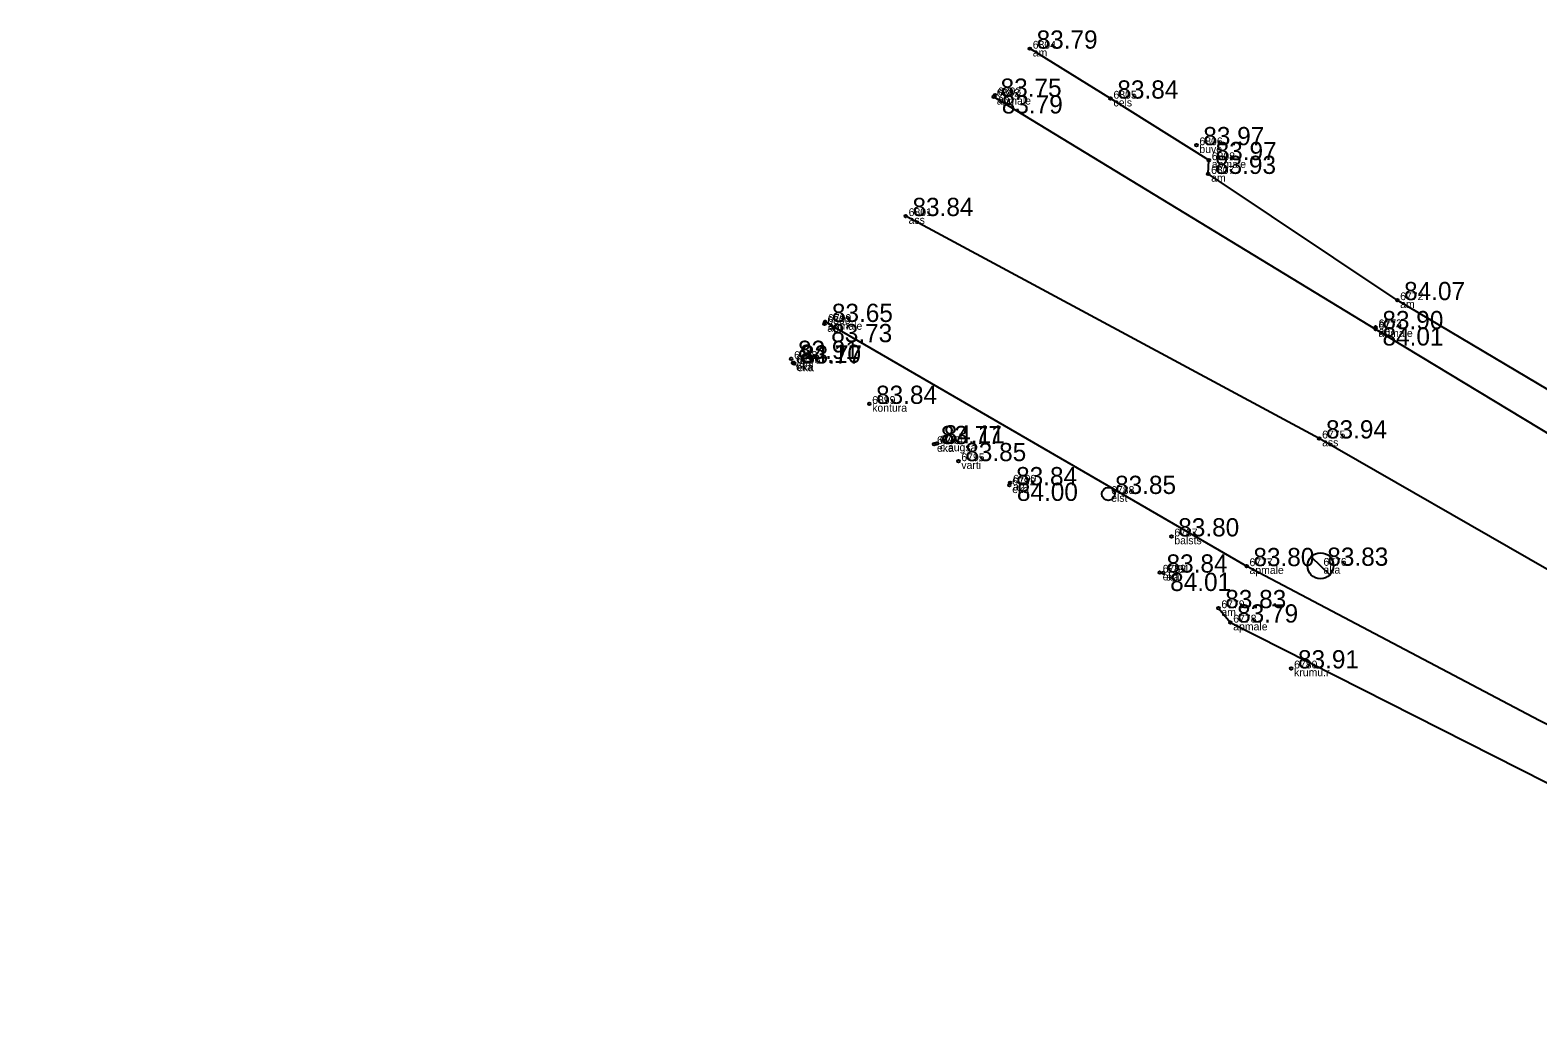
# Model space of a CAD drawing. Extents: x 614911 to 615803, y 262110 to 264311.
# Drawn here: x 615140.5 to 615198.4, y 262553.3 to 262591 of the extents above; entities that cross this region are included whole.
import ezdxf

# ---------------------------------------------------------------- set-up
doc = ezdxf.new("R2010")
doc.units = 0
for name, color, linetype in [('Level 12', 7, 'Continuous'), ('Level 18', 7, 'Continuous'), ('Level 37', 7, 'Continuous'), ('Level 53', 7, 'Continuous'), ('Level 54', 7, 'Continuous'), ('Level 57', 7, 'Continuous'), ('Level 58', 7, 'Continuous')]:
    doc.layers.add(name, color=color, linetype=linetype)

msp = doc.modelspace()

# ---------------------------------------------------------------- linework, layer by layer
at = {"layer": 'Level 12'}
for p, q in [((615189.679, 262570.789), (615190.397, 262570.093)), ((615190.038, 262570.441), (615190.037, 262570.44))]:
    msp.add_line(p, q, dxfattribs=at)
msp.add_circle((615190.038, 262570.441), 0.5, dxfattribs=at)
at = {"layer": 'Level 18'}
msp.add_circle((615181.889, 262573.199), 0.25, dxfattribs=at)
at = {"layer": 'Level 37'}
for p, q in [((615186.12, 262568.814), (615186.576, 262568.261)), ((615186.576, 262568.261), (615202.324, 262560.29))]:
    msp.add_line(p, q, dxfattribs=at)
for points in [[(615208.683, 262572.181), (615199.6, 262576.716), (615192.986, 262580.641), (615185.727, 262585.487), (615185.75, 262586.016), (615181.977, 262588.379), (615178.877, 262590.297)], [(615177.494, 262588.45), (615192.153, 262579.526), (615207.523, 262570.238), (615220.011, 262562.863), (615221.634, 262562.045), (615224.342, 262561.098), (615229.242, 262561.003), (615229.462, 262561.056)], [(615216.216, 262560.276), (615189.988, 262575.33), (615174.111, 262583.87)], [(615134.751, 262536.316), (615136.666, 262532.387), (615152.21, 262536.845), (615168.777, 262541.517), (615176.69, 262543.827), (615195.4, 262549.214), (615198.892, 262550.172), (615209.293, 262553.06), (615211.306, 262553.645), (615214.425, 262554.554), (615214.157, 262556.702), (615205.474, 262561.046), (615198.438, 262564.498), (615187.2, 262570.428), (615171.016, 262579.803)]]:
    msp.add_lwpolyline(points, dxfattribs=at)
at = {"layer": 'Level 57'}
for centre in [(615178.877, 262590.297), (615177.494, 262588.45), (615177.54, 262588.508), (615181.977, 262588.379), (615185.277, 262586.59), (615185.727, 262585.487), (615185.75, 262586.016), (615174.111, 262583.87), (615192.986, 262580.641), (615170.99, 262579.726), (615171.016, 262579.803), (615192.153, 262579.526), (615192.158, 262579.599), (615169.714, 262578.384), (615169.791, 262578.231), (615169.83, 262578.206), (615172.713, 262576.657), (615175.201, 262575.113), (615175.309, 262575.14), (615189.988, 262575.33), (615176.136, 262574.459), (615178.09, 262573.533), (615178.12, 262573.633), (615184.314, 262571.569), (615187.2, 262570.428), (615183.865, 262570.179), (615184.005, 262570.173), (615186.12, 262568.814), (615186.576, 262568.261), (615188.913, 262566.501)]:
    msp.add_circle(centre, 0.05, dxfattribs=at)
at = {"layer": 'Level 58'}
for centre in [(615178.877, 262590.297), (615177.494, 262588.45), (615177.54, 262588.508), (615181.977, 262588.379), (615185.277, 262586.59), (615185.727, 262585.487), (615185.75, 262586.016), (615174.111, 262583.87), (615192.986, 262580.641), (615170.99, 262579.726), (615171.016, 262579.803), (615192.153, 262579.526), (615192.158, 262579.599), (615169.714, 262578.384), (615169.791, 262578.231), (615169.83, 262578.206), (615172.713, 262576.657), (615175.201, 262575.113), (615175.309, 262575.14), (615189.988, 262575.33), (615176.136, 262574.459), (615178.09, 262573.533), (615178.12, 262573.633), (615184.314, 262571.569), (615187.2, 262570.428), (615183.865, 262570.179), (615184.005, 262570.173), (615186.12, 262568.814), (615186.576, 262568.261), (615188.913, 262566.501)]:
    msp.add_circle(centre, 0.05, dxfattribs=at)

# ---------------------------------------------------------------- texts
at = {"layer": 'Level 53'}
for s, p in [(' am', (615178.877, 262589.997)), (' apmale', (615177.494, 262588.15)), (' ap', (615177.54, 262588.208)), (' cels', (615181.977, 262588.079)), (' buve', (615185.277, 262586.29)), (' apmale', (615185.75, 262585.716)), (' am', (615185.727, 262585.187)), (' ass', (615174.111, 262583.57)), (' am', (615192.986, 262580.341)), (' apmale', (615171.016, 262579.503)), (' ap', (615170.99, 262579.426)), (' apmale', (615192.153, 262579.226)), (' ap', (615192.158, 262579.299)), (' varti', (615169.714, 262578.084)), (' eka', (615169.791, 262577.931)), (' eka', (615169.83, 262577.906)), (' kontura', (615172.713, 262576.357)), (' eka', (615175.201, 262574.813)), (' ass', (615189.988, 262575.03)), (' c.augsa', (615175.309, 262574.84)), (' varti', (615176.136, 262574.159)), (' eka', (615178.09, 262573.233)), (' ap', (615178.12, 262573.333)), (' elst', (615181.889, 262572.899)), (' balsts', (615184.314, 262571.269)), (' aka', (615190.038, 262570.141)), (' eka', (615183.865, 262569.879)), (' ap', (615184.005, 262569.873)), (' apmale', (615187.2, 262570.128)), (' am', (615186.12, 262568.514)), (' apmale', (615186.576, 262567.961)), (' krumu.r', (615188.913, 262566.201))]:
    msp.add_text(s, height=0.3, dxfattribs=at).set_placement(p)
at = {"layer": 'Level 54'}
for s, p in [(' 6804', (615178.877, 262590.297)), (' 6802', (615177.494, 262588.45)), (' 6803', (615177.54, 262588.508)), (' 6805', (615181.977, 262588.379)), (' 6806', (615185.277, 262586.59)), (' 6808', (615185.75, 262586.016)), (' 6807', (615185.727, 262585.487)), (' 6801', (615174.111, 262583.87)), (' 6772', (615192.986, 262580.641)), (' 6800', (615170.99, 262579.726)), (' 6799', (615171.016, 262579.803)), (' 6774', (615192.153, 262579.526)), (' 6773', (615192.158, 262579.599)), (' 6798', (615169.714, 262578.384)), (' 6797', (615169.791, 262578.231)), (' 6796', (615169.83, 262578.206)), (' 6899', (615172.713, 262576.657)), (' 6793', (615175.201, 262575.113)), (' 6794', (615175.309, 262575.14)), (' 6775', (615189.988, 262575.33)), (' 6795', (615176.136, 262574.459)), (' 6790', (615178.12, 262573.633)), (' 6792', (615178.09, 262573.533)), (' 6788', (615181.889, 262573.199)), (' 6787', (615184.314, 262571.569)), (' 6789', (615183.865, 262570.179)), (' 6791', (615184.005, 262570.173)), (' 6777', (615187.2, 262570.428)), (' 6776', (615190.038, 262570.441)), (' 6779', (615186.12, 262568.814)), (' 6778', (615186.576, 262568.261)), (' 6780', (615188.913, 262566.501))]:
    msp.add_text(s, height=0.3, dxfattribs=at).set_placement(p)
at = {"layer": 'Level 58'}
for s, p in [(' 83.79', (615178.877, 262590.297)), (' 83.75', (615177.494, 262588.45)), (' 83.84', (615181.977, 262588.379)), (' 83.79', (615177.54, 262587.808)), (' 83.97', (615185.277, 262586.59)), (' 83.97', (615185.75, 262586.016)), (' 83.93', (615185.727, 262585.487)), (' 83.84', (615174.111, 262583.87)), (' 84.07', (615192.986, 262580.641)), (' 83.65', (615171.016, 262579.803)), (' 83.73', (615170.99, 262579.026)), (' 83.90', (615192.153, 262579.526)), (' 84.01', (615192.158, 262578.899)), (' 83.91', (615169.714, 262578.384)), (' 84.10', (615169.791, 262578.231)), (' 83.77', (615169.83, 262578.206)), (' 83.84', (615172.713, 262576.657)), (' 83.77', (615175.201, 262575.113)), (' 84.11', (615175.309, 262575.14)), (' 83.94', (615189.988, 262575.33)), (' 83.85', (615176.136, 262574.459)), (' 83.84', (615178.09, 262573.533)), (' 84.00', (615178.12, 262572.933)), (' 83.85', (615181.889, 262573.199)), (' 83.80', (615184.314, 262571.569)), (' 83.80', (615187.2, 262570.428)), (' 83.83', (615190.038, 262570.441)), (' 83.84', (615183.865, 262570.179)), (' 84.01', (615184.005, 262569.473)), (' 83.83', (615186.12, 262568.814)), (' 83.79', (615186.576, 262568.261)), (' 83.91', (615188.913, 262566.501))]:
    msp.add_text(s, height=0.7, dxfattribs=at).set_placement(p)

doc.saveas('drawing.dxf')
